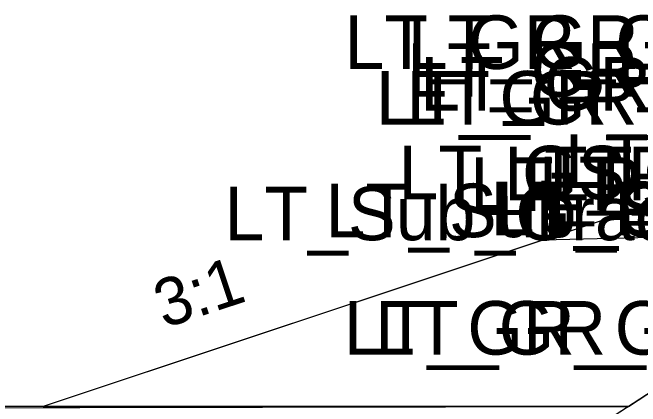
# Model space of a CAD drawing. Extents: x -14026 to 1303, y -10 to 9533.
# Drawn here: x 114.52 to 127.7, y 5503.4 to 5511.67 of the extents above; entities that cross this region are included whole.
import ezdxf

# ---------------------------------------------------------------- set-up
doc = ezdxf.new("R2010")
doc.units = 0
for name, color, linetype in [('Exist XS Ground Line', 7, 'Continuous'), ('Old_Level_10', 7, 'Continuous'), ('Prop CMT Slope Grass', 7, 'Continuous'), ('Prop CMT Subgrade Earthwork', 7, 'Continuous'), ('Prop XS Earthwork Shape', 7, 'Continuous'), ('Prop XS Side Slope Text', 7, 'Continuous'), ('Scratch_Level_0', 7, 'Continuous'), ('Scratch_Level_3', 7, 'Continuous')]:
    doc.layers.add(name, color=color, linetype=linetype)

msp = doc.modelspace()

# ---------------------------------------------------------------- linework, layer by layer
at = {"layer": 'Exist XS Ground Line'}
msp.add_lwpolyline([(109.468, 5501.405), (116.444, 5501.148), (124.17, 5501.35), (125.591, 5502.188), (128.813, 5504.283), (129.516, 5504.716), (132.664, 5505.441), (133.561, 5505.769), (135.449, 5506.3), (138.238, 5507.084), (139.438, 5507.159), (142.97, 5507.319), (144.696, 5507.918), (145.236, 5508.101), (147.943, 5508.043), (150, 5507.997), (156.053, 5507.859), (165.752, 5508.467)], dxfattribs=at)
at = {"layer": 'Old_Level_10'}
msp.add_lwpolyline([(116.444, 5501.148), (109.089, 5501.37), (112.089, 5503.37), (127.449, 5503.396), (125.911, 5502.396), (124.17, 5501.35)], close=True, dxfattribs=at)
at = {"layer": 'Prop CMT Slope Grass'}
msp.add_line((115.167, 5503.396), (127.449, 5503.396), dxfattribs=at)
msp.add_lwpolyline([(128.225, 5507.745), (115.167, 5503.396)], dxfattribs=at)
at = {"layer": 'Prop CMT Subgrade Earthwork'}
msp.add_line((115.167, 5503.396), (127.449, 5503.396), dxfattribs=at)
for points in [[(125.65, 5506.887), (115.167, 5503.396)], [(128.225, 5506.951), (125.65, 5506.887)]]:
    msp.add_lwpolyline(points, dxfattribs=at)
at = {"layer": 'Prop XS Earthwork Shape'}
for points in [[(129.516, 5504.716), (132.664, 5505.441), (133.561, 5505.769), (135.449, 5506.3), (138.238, 5507.084), (139.438, 5507.159), (142.97, 5507.319), (144.696, 5507.918), (145.236, 5508.101), (147.943, 5508.043), (150, 5507.997), (156.053, 5507.859), (161.109, 5508.176), (150, 5508.454), (142.97, 5508.278), (138, 5508.154), (131.226, 5507.985), (128.225, 5507.745), (115.167, 5503.396), (127.449, 5503.396), (128.813, 5504.283)], [(142.97, 5507.319), (138, 5507.196), (129.743, 5506.989), (128.225, 5506.951), (125.65, 5506.887), (115.167, 5503.396), (127.449, 5503.396), (128.813, 5504.283), (129.516, 5504.716), (132.664, 5505.441), (133.561, 5505.769), (135.449, 5506.3), (138.238, 5507.084), (139.438, 5507.159)]]:
    msp.add_lwpolyline(points, close=True, dxfattribs=at)
at = {"layer": 'Scratch_Level_3'}
msp.add_line((127.449, 5503.396), (101.898, 5503.396), dxfattribs=at)

# ---------------------------------------------------------------- texts
at = {"layer": 'Prop XS Side Slope Text'}
msp.add_text('3:1', height=1, rotation=18.4178, dxfattribs=at).set_placement((117.704, 5505.031))
at = {"layer": 'Scratch_Level_0'}
for s, p in [('LT_GR_Graphics Out 03', (121.491, 5510.484)), ('LT_GR_Graphics Out 02', (122.818, 5510.484)), ('LT_GR_Out', (127.194, 5510.192)), ('LT_GR_Graphics Out 09', (122.808, 5509.9)), ('LT_GR_Graphics Out 08', (123.078, 5509.609)), ('LT_GR_Graphics Out 06', (122.151, 5509.317)), ('LT_GR_Graphics Out 07', (122.789, 5509.317)), ('LT_PS1_OEOP', (126.118, 5507.985)), ('LT_GS_OS_CTL', (122.625, 5507.745)), ('LT_PS2_Shelf Out', (124.842, 5507.728)), ('LT_PS2_OEOP', (125.785, 5507.728)), ('LT_PS3_Shelf Out', (124.128, 5507.502)), ('LT_PS3_OEOP', (125.571, 5507.515)), ('LT_Sub_OEOP', (124.646, 5506.989)), ('LT_Sub_Graded_Tie', (118.971, 5506.887)), ('LT_Sub_Graded_CTL', (121.091, 5506.951)), ('LT_PS4_OEOP', (124.558, 5506.989)), ('LT_GR_Graphics Out 04', (121.477, 5504.484)), ('LT_GR_Graphics Out 05', (122.134, 5504.484))]:
    msp.add_text(s, height=1.125, dxfattribs=at).set_placement(p)

doc.saveas('drawing.dxf')
